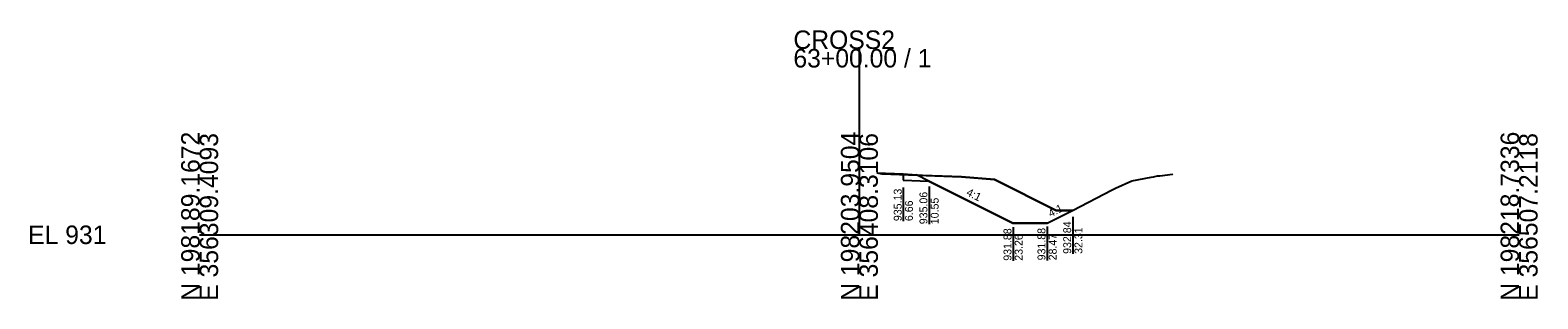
# Model space of a CAD drawing. Extents: x -26 to 203, y -10 to 14021.
# Drawn here: x -25.7 to 202.8, y 3990.3 to 4031 of the extents above; entities that cross this region are included whole.
import ezdxf

# ---------------------------------------------------------------- set-up
doc = ezdxf.new("R2010")
doc.units = 0
for name, color, linetype in [('Default', 7, 'Continuous'), ('P_E_XS_Ground', 7, 'Continuous'), ('P_XS', 7, 'Continuous'), ('P_XS_EAR_CommonGrnd', 7, 'Continuous'), ('P_XS_Lane', 7, 'Continuous'), ('P_XS_Rock', 7, 'Continuous')]:
    doc.layers.add(name, color=color, linetype=linetype)

msp = doc.modelspace()

# ---------------------------------------------------------------- linework, layer by layer
at = {"layer": 'Default'}
for p, q in [((100, 4000), (100, 4028.13)), ((0, 4000), (100, 4000)), ((100, 4000), (200, 4000))]:
    msp.add_line(p, q, dxfattribs=at)
at = {"layer": 'P_E_XS_Ground'}
for p, q in [((102.66, 4009.38), (103.13, 4009.26)), ((103.13, 4009.26), (103.41, 4009.23)), ((103.41, 4009.23), (115.5, 4008.75)), ((115.5, 4008.75), (120.5, 4008.35)), ((141.28, 4008.15), (144.21, 4008.72)), ((144.21, 4008.72), (144.59, 4008.79)), ((144.59, 4008.79), (145.18, 4008.92)), ((145.18, 4008.92), (145.52, 4008.92)), ((145.52, 4008.92), (147.47, 4009.2)), ((147.47, 4009.2), (147.5, 4009.23)), ((120.5, 4008.35), (129.84, 4003.68)), ((132.31, 4003.68), (138.31, 4006.79)), ((138.31, 4006.79), (138.84, 4007.04)), ((138.84, 4007.04), (141.28, 4008.15)), ((129.84, 4003.68), (132.31, 4003.68))]:
    msp.add_line(p, q, dxfattribs=at)
at = {"layer": 'P_XS'}
for p, q in [((102.66, 4009.38), (106.66, 4009.22)), ((106.66, 4009.22), (108.66, 4009.06)), ((110.55, 4008.11), (108.66, 4009.06))]:
    msp.add_line(p, q, dxfattribs=at)
at = {"layer": 'P_XS_EAR_CommonGrnd'}
msp.add_lwpolyline([(106.66, 4008.27), (110.55, 4008.11), (123.26, 4001.76), (128.47, 4001.76), (132.31, 4003.68), (129.84, 4003.68), (120.5, 4008.35), (115.5, 4008.75), (106.66, 4009.1)], close=True, dxfattribs=at)
at = {"layer": 'P_XS_Lane'}
for p, q in [((106.66, 4009.1), (106.66, 4008.27)), ((106.66, 4008.27), (110.55, 4008.11)), ((123.26, 4001.76), (110.55, 4008.11)), ((128.47, 4001.76), (123.26, 4001.76)), ((128.47, 4001.76), (132.31, 4003.68))]:
    msp.add_line(p, q, dxfattribs=at)
at = {"layer": 'P_XS_Rock'}
for p, q in [((106.66, 4007.17), (106.66, 4002.07)), ((110.56, 4007.29), (110.56, 4001.6)), ((132.35, 4002.7), (132.35, 3997.11)), ((123.3, 4001.17), (123.3, 3996.07)), ((128.45, 4001.23), (128.45, 3996.13))]:
    msp.add_line(p, q, dxfattribs=at)

# ---------------------------------------------------------------- texts
at = {"layer": 'Default'}
for s, p in [('CROSS2', (90, 4028.13)), ('63+00.00 / 1', (90, 4025.33)), ('EL 931', (-26, 3998.6))]:
    msp.add_text(s, height=2.8, dxfattribs=at).set_placement(p)
for s, p in [('N 198189.1672', (0, 3990)), ('N 198203.9504', (100, 3990)), ('N 198218.7336', (200, 3990)), ('E 356309.4093', (2.8, 3990)), ('E 356408.3106', (102.8, 3990)), ('E 356507.2118', (202.8, 3990))]:
    msp.add_text(s, height=2.8, rotation=90, dxfattribs=at).set_placement(p)
at = {"layer": 'P_XS_Rock'}
for s, rotation, p in [('935.13', 90, (106.41, 4002.07)), ('935.06', 90, (110.31, 4001.6)), ('4:1', 333.4349, (116.1, 4006.04)), ('6.66', 90, (108.11, 4002.07)), ('10.55', 90, (112.01, 4001.6)), ('4:1', 26.5651, (128.99, 4002.63)), ('932.84', 90, (132.1, 3997.11)), ('931.88', 90, (123.05, 3996.07)), ('23.26', 90, (124.75, 3996.07)), ('931.88', 90, (128.2, 3996.13)), ('28.47', 90, (129.9, 3996.13)), ('32.31', 90, (133.8, 3997.11))]:
    msp.add_text(s, height=1.2, rotation=rotation, dxfattribs=at).set_placement(p)

doc.saveas('drawing.dxf')
